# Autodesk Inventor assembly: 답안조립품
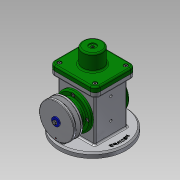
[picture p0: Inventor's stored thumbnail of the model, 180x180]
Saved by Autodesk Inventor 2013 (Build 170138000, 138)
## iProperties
Created: 2019-08
Part Number: 답안조립품
Document SubType Name: Assembly
Designer: hana-max10
Author: hana-max10
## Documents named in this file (18)
- C:\Documents and Settings\hana-max10\바탕 화면\490804V1013\답안조립품.iam
- C:\Documents and Settings\hana-max10\바탕 화면\490804V1013\본체.ipt
- C:\Documents and Settings\hana-max10\바탕 화면\490804V1013\편심축.ipt
- C:\Documents and Settings\hana-max10\바탕 화면\490804V1013\베어링 17 x 40 x 12.ipt
- C:\Documents and Settings\hana-max10\바탕 화면\490804V1013\뒤커버.ipt
- C:\Documents and Settings\hana-max10\바탕 화면\490804V1013\볼트 M4 x 8.ipt
- C:\Documents and Settings\hana-max10\바탕 화면\490804V1013\앞커버.ipt
- C:\Documents and Settings\hana-max10\바탕 화면\490804V1013\오일 실 17 30 8.ipt
- C:\Documents and Settings\hana-max10\바탕 화면\490804V1013\키 4 x 4 x 12.ipt
- C:\Documents and Settings\hana-max10\바탕 화면\490804V1013\V-벨트풀리.ipt
- C:\Documents and Settings\hana-max10\바탕 화면\490804V1013\와셔 4x16.ipt
- C:\Documents and Settings\hana-max10\바탕 화면\490804V1013\볼트 M4 x 10.ipt
- C:\Documents and Settings\hana-max10\바탕 화면\490804V1013\링크.ipt
- C:\Documents and Settings\hana-max10\바탕 화면\490804V1013\슬라이더.ipt
- C:\Documents and Settings\hana-max10\바탕 화면\490804V1013\클레비스 핀 6 x 22.ipt
- 클레비스 핀 6 x 22.ipt
- C:\Documents and Settings\hana-max10\바탕 화면\490804V1013\덮개.ipt
- C:\Documents and Settings\hana-max10\바탕 화면\490804V1013\E-링.ipt
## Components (2 placed, 2 different names)
1. V-벨트풀리:1
2. E-링:1
